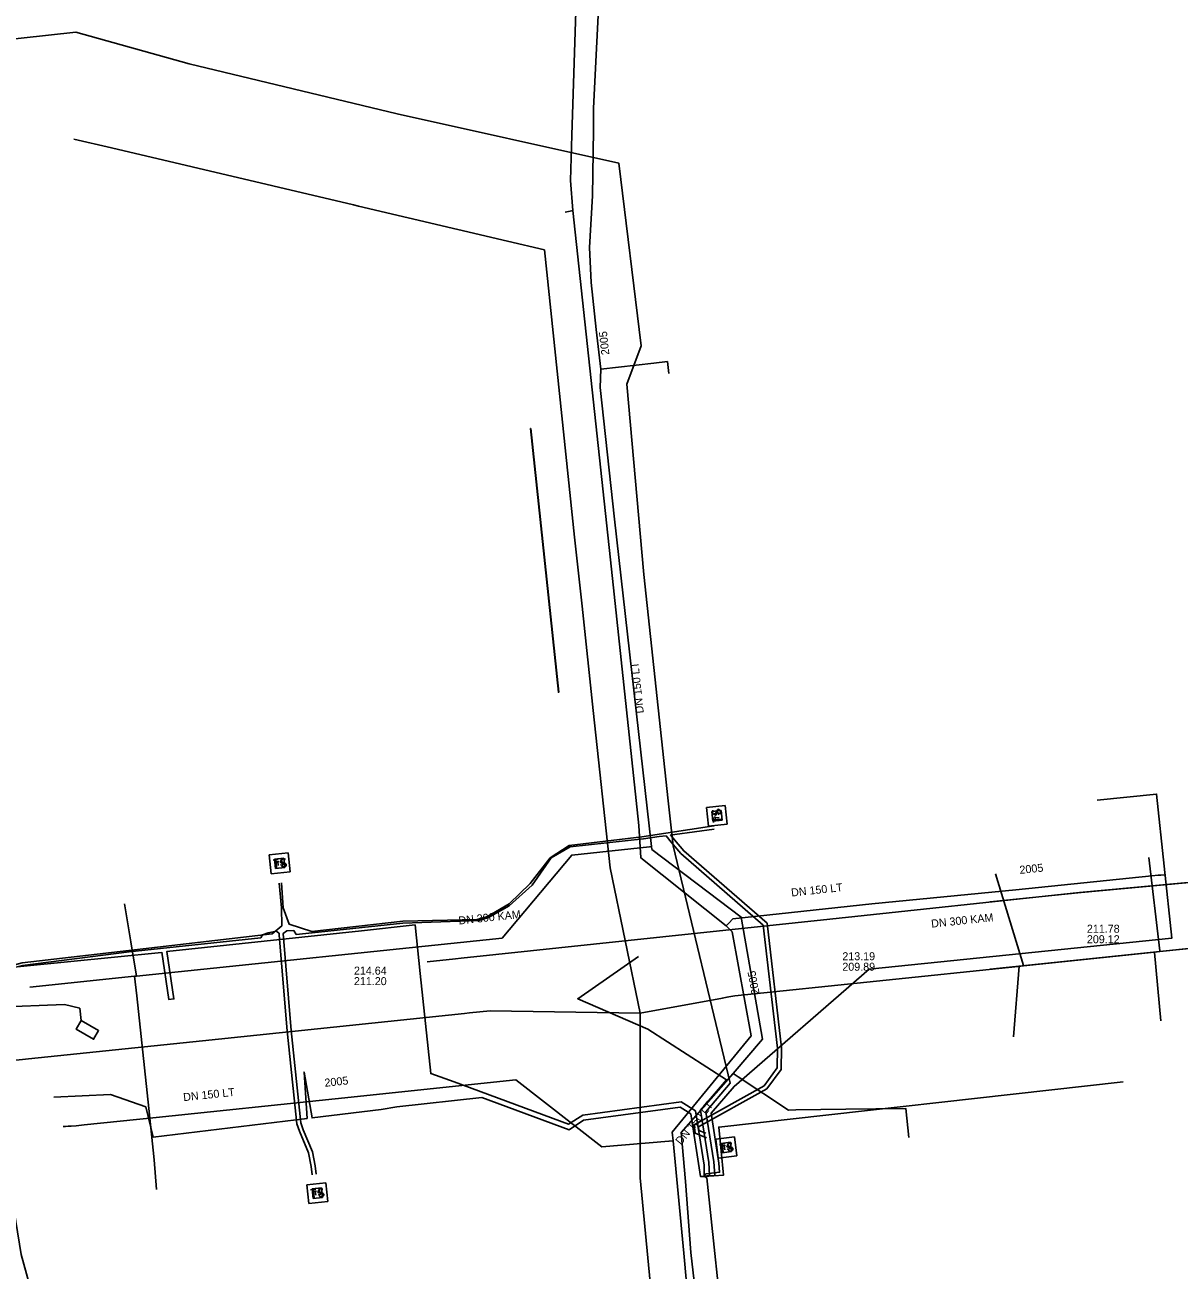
# Model space of a CAD drawing. Extents: x -599951 to -598963, y -1164095 to -1162939.
# Drawn here: x -599185.3 to -599070, y -1163320.1 to -1163195.6 of the extents above; entities that cross this region are included whole.
import ezdxf

# ---------------------------------------------------------------- set-up
doc = ezdxf.new("R2010")
doc.units = 0
for name, color, linetype in [('25', 7, 'Continuous'), ('Level 1', 7, 'Continuous'), ('Level 3', 7, 'Continuous'), ('Vrstva 1', 7, 'Continuous'), ('Vrstva 13', 7, 'Continuous'), ('Vrstva 15', 7, 'Continuous'), ('Vrstva 19', 7, 'Continuous'), ('Vrstva 42', 7, 'Continuous'), ('Vrstva 43', 7, 'Continuous'), ('Vrstva 44', 7, 'Continuous'), ('Vrstva 45', 7, 'Continuous'), ('Vrstva 5', 7, 'Continuous'), ('Vrstva 55', 7, 'Continuous'), ('Vrstva 8', 7, 'Continuous')]:
    doc.layers.add(name, color=color, linetype=linetype)

# ---------------------------------------------------------------- blocks, each defined once
blk = doc.blocks.new('VN640')
at = {"layer": '25'}
for points in [[(-1.89, 1.889), (1.889, 1.889)], [(-1.89, -1.89), (-1.89, 1.889)], [(-1.26, 0.787), (-0.221, 0.787)], [(-0.725, 0.787), (-0.725, -0.788)], [(1.197, 0.661), (0.945, 0.787), (0.661, 0.787), (0.409, 0.661), (0.283, 0.472), (0.283, 0.409), (0.409, 0.22), (1.133, -0.158), (1.259, -0.316), (1.259, -0.473), (1.133, -0.662), (0.913, -0.788), (0.629, -0.788), (0.503, -0.725), (0.283, -0.599)], [(1.889, 1.889), (1.889, -1.89)], [(1.889, -1.89), (-1.89, -1.89)]]:
    blk.add_lwpolyline(points, dxfattribs=at)
blk = doc.blocks.new('NN640')
at = {"layer": '25'}
for points in [[(-1.89, 1.889), (1.889, 1.889)], [(-1.89, -1.89), (-1.89, 1.889)], [(-1.26, 0.787), (-0.221, 0.787)], [(-0.725, 0.787), (-0.725, -0.788)], [(1.197, 0.661), (0.945, 0.787), (0.661, 0.787), (0.409, 0.661), (0.283, 0.472), (0.283, 0.409), (0.409, 0.22), (1.133, -0.158), (1.259, -0.316), (1.259, -0.473), (1.133, -0.662), (0.913, -0.788), (0.629, -0.788), (0.503, -0.725), (0.283, -0.599)], [(1.889, 1.889), (1.889, -1.89)], [(1.889, -1.89), (-1.89, -1.89)]]:
    blk.add_lwpolyline(points, dxfattribs=at)

msp = doc.modelspace()

# ---------------------------------------------------------------- linework, layer by layer
at = {"layer": 'Level 1'}
for points in [[(-599073.04, -1163278.86), (-599071.92, -1163288.19)], [(-599088.87, -1163283.31), (-599079.8, -1163282.35), (-599054.91, -1163280.08)], [(-599088.35, -1163280.51), (-599085.55, -1163289.65)], [(-599088.87, -1163290.03), (-599064.91, -1163287.54)], [(-599071.84, -1163295.18), (-599072.46, -1163288.36)], [(-599086.55, -1163296.78), (-599085.99, -1163289.73)], [(-599121.08, -1163339.75), (-599123.86, -1163310.87)]]:
    msp.add_lwpolyline(points, dxfattribs=at)
at = {"layer": 'Level 3'}
msp.add_lwpolyline([(-599134.774, -1163235.992), (-599131.993, -1163262.35), (-599132.026, -1163262.352), (-599134.809, -1163235.998)], close=True, dxfattribs=at)
at = {"layer": 'Vrstva 1'}
for p, q in [((-599133.4, -1163218.12), (-599130.4, -1163246.83)), ((-599126.86, -1163279.89), (-599123.848, -1163294.424)), ((-599138.824, -1163294.187), (-599123.848, -1163294.424)), ((-599123.86, -1163310.87), (-599123.848, -1163294.424))]:
    msp.add_line(p, q, dxfattribs=at)
for points in [[(-599180.431, -1163207.06), (-599176.662, -1163207.946), (-599152.489, -1163213.631), (-599151.996, -1163213.747), (-599137.108, -1163217.248), (-599133.4, -1163218.12)], [(-599130.4, -1163246.83), (-599129.66, -1163253.739), (-599128.542, -1163264.18), (-599126.86, -1163279.89)], [(-599114.398, -1163292.695), (-599086.084, -1163289.744), (-599085.537, -1163289.687), (-599072.458, -1163288.324), (-599071.911, -1163288.267), (-599065.048, -1163287.552)], [(-599123.848, -1163294.424), (-599115.628, -1163292.92), (-599115.185, -1163292.839), (-599114.398, -1163292.695)], [(-599167.579, -1163297.182), (-599141.41, -1163294.457), (-599140.913, -1163294.405), (-599138.824, -1163294.187)], [(-599188.263, -1163299.327), (-599185.582, -1163299.049), (-599184.986, -1163298.987), (-599167.579, -1163297.182)]]:
    msp.add_lwpolyline(points, dxfattribs=at)
at = {"layer": 'Vrstva 13'}
for p, q in [((-599071.837, -1163280.62), (-599071.41, -1163280.59)), ((-599072.099, -1163280.646), (-599071.837, -1163280.62)), ((-599115.26, -1163285.71), (-599114.99, -1163285.42)), ((-599181.262, -1163305.746), (-599181.49, -1163305.76)), ((-599181, -1163305.73), (-599181.262, -1163305.746)), ((-599180.711, -1163305.708), (-599181, -1163305.73)), ((-599120.54, -1163307.19), (-599120.963, -1163307.228))]:
    msp.add_line(p, q, dxfattribs=at)
for points in [[(-599129.94, -1163183.95), (-599130.67, -1163206.65), (-599130.8, -1163211.19), (-599130.57, -1163214.21)], [(-599130.57, -1163214.21), (-599130.86, -1163214.27), (-599131.33, -1163214.37)], [(-599130.57, -1163214.21), (-599126.71, -1163250.03), (-599124, -1163275.68), (-599123.77, -1163278.9), (-599115.26, -1163285.71)], [(-599114.99, -1163285.42), (-599114.59, -1163284.99), (-599100.72, -1163283.51), (-599086.3, -1163282.09), (-599072.73, -1163280.71), (-599072.099, -1163280.646)], [(-599115.26, -1163285.71), (-599114.66, -1163286.31), (-599112.76, -1163296.68), (-599120.64, -1163306.32), (-599120.54, -1163307.19)], [(-599120.963, -1163307.228), (-599120.99, -1163307.23), (-599127.67, -1163307.77), (-599136.28, -1163301.09), (-599154.33, -1163302.99), (-599172.22, -1163304.86), (-599179.403, -1163305.585), (-599180.21, -1163305.67), (-599180.711, -1163305.708)], [(-599120.54, -1163307.19), (-599119.5, -1163318.42), (-599118.91, -1163324.7), (-599114.698, -1163364.679), (-599114.5, -1163366.64)]]:
    msp.add_lwpolyline(points, dxfattribs=at)
at = {"layer": 'Vrstva 19'}
for points in [[(-599126.75, -1163162.08), (-599126.79, -1163163.73), (-599127.2, -1163178.52), (-599127.22, -1163178.72), (-599127.28, -1163179.39), (-599127.45, -1163182.79), (-599127.55, -1163184.72), (-599128.5, -1163203.98), (-599128.53, -1163206.15), (-599128.61, -1163212.73), (-599128.92, -1163217.9), (-599128.75, -1163221.4), (-599128.24, -1163226.08), (-599127.78, -1163230.06), (-599127.84, -1163231.89), (-599126.43, -1163245.05), (-599122.72, -1163277.78), (-599122.68, -1163278.05), (-599113.77, -1163284.82), (-599111.62, -1163297.03), (-599114.57, -1163300.46), (-599119.76, -1163306.35), (-599119.31, -1163311.26)], [(-599127.78, -1163230.06), (-599122.47, -1163229.45)], [(-599122.47, -1163229.45), (-599121.13, -1163229.29), (-599120.98, -1163230.49)], [(-599122.92, -1163277.8), (-599130.68, -1163278.63), (-599137.65, -1163286.92), (-599174.17, -1163290.72), (-599174.37, -1163290.74), (-599184.83, -1163291.83)], [(-599122.72, -1163277.78), (-599122.92, -1163277.8)], [(-599175.38, -1163283.5), (-599174.74, -1163287.31), (-599174.17, -1163290.72)], [(-599174.37, -1163290.74), (-599174.16, -1163292.69), (-599172.95, -1163303.94), (-599172.4, -1163309.1), (-599172.18, -1163312.05)], [(-599114.57, -1163300.46), (-599114.06, -1163300.79), (-599109.02, -1163304.11), (-599108.3, -1163304.1)], [(-599108.299, -1163304.101), (-599103.302, -1163304.026), (-599097.308, -1163303.938), (-599097.018, -1163306.838)], [(-599119.31, -1163311.26), (-599118.79, -1163318.36), (-599116.95, -1163334.26), (-599115.29, -1163352.21), (-599112.46, -1163377.65), (-599112.44, -1163377.84)]]:
    msp.add_lwpolyline(points, dxfattribs=at)
at = {"layer": 'Vrstva 42'}
for p, q in [((-599190.603, -1163293.916), (-599181.368, -1163293.563)), ((-599181.368, -1163293.563), (-599179.853, -1163293.926))]:
    msp.add_line(p, q, dxfattribs=at)
for points in [[(-599189.356, -1163255.904), (-599189.27, -1163255.9), (-599188.93, -1163256.56), (-599189.33, -1163266.86), (-599190.19, -1163270.28), (-599190.39, -1163272.54), (-599189.34, -1163289.98), (-599189, -1163294.5), (-599187.674, -1163304.188), (-599186.96, -1163310.71), (-599185.69, -1163318.54), (-599183.37, -1163327.02), (-599181.88, -1163329.78), (-599181.18, -1163331.7), (-599178.4, -1163350.09), (-599176.426, -1163364.646), (-599174.91, -1163374.22), (-599174.01, -1163382.86), (-599173.53, -1163386.1), (-599173.83, -1163387.31), (-599174.41, -1163387.97), (-599176.305, -1163391.004)], [(-599179.853, -1163293.926), (-599179.701, -1163295.167), (-599180.202, -1163296.032), (-599178.471, -1163297.034), (-599177.97, -1163296.169), (-599179.701, -1163295.167)]]:
    msp.add_lwpolyline(points, dxfattribs=at)
at = {"layer": 'Vrstva 44'}
for points in [[(-599161.6, -1163286.61), (-599161.768, -1163286.882), (-599174.92, -1163288.29), (-599185.56, -1163289.67), (-599188.76, -1163290.47), (-599253.7, -1163297.18), (-599254.76, -1163296.51), (-599255.896, -1163293.057), (-599256.264, -1163290.876), (-599256.287, -1163290.145), (-599256.603, -1163287.926), (-599258.874, -1163253.063), (-599260.496, -1163226.149), (-599261.652, -1163202.746), (-599261.6, -1163195.999), (-599261.001, -1163188.45)], [(-599159.684, -1163281.406), (-599159.52, -1163283.88), (-599158.92, -1163285.54), (-599156.65, -1163286.27), (-599147.57, -1163285.24), (-599140.14, -1163285.05), (-599139.09, -1163284.76), (-599136.95, -1163283.51), (-599134.83, -1163281.46), (-599132.83, -1163278.91), (-599130.96, -1163277.65), (-599123.67, -1163276.79), (-599116.496, -1163275.683)], [(-599121.256, -1163276.69), (-599121.952, -1163276.782), (-599123.52, -1163277), (-599130.84, -1163277.79), (-599132.75, -1163278.89), (-599134.64, -1163281.64), (-599136.94, -1163283.68), (-599139, -1163284.87), (-599139.96, -1163285.16), (-599147.57, -1163285.44), (-599156.62, -1163286.41), (-599158.212, -1163286.547), (-599158.45, -1163286.17)], [(-599117.236, -1163306.876), (-599118.365, -1163306.421), (-599118.464, -1163305.57), (-599111.475, -1163301.676), (-599110.149, -1163299.902), (-599110.12, -1163297.92), (-599111.55, -1163285.64), (-599119.783, -1163278.481), (-599120.745, -1163277.346), (-599121.256, -1163276.69)], [(-599116.458, -1163276.026), (-599120.384, -1163276.567), (-599120.812, -1163276.615)], [(-599120.812, -1163276.615), (-599120.424, -1163277.106), (-599119.497, -1163278.199), (-599111.17, -1163285.44), (-599109.72, -1163297.9), (-599109.751, -1163300.038), (-599111.205, -1163301.984), (-599118.036, -1163305.79), (-599117.995, -1163306.139), (-599117.287, -1163306.423)], [(-599252.79, -1163297.02), (-599251.6, -1163296.924), (-599251.285, -1163296.822), (-599250.535, -1163296.649), (-599188.84, -1163290.26), (-599185.61, -1163289.38), (-599174.94, -1163288.15), (-599160.62, -1163286.51), (-599159.66, -1163285.71), (-599159.7, -1163283.9), (-599159.915, -1163281.43)], [(-599156.618, -1163310.576), (-599156.728, -1163309.742), (-599156.983, -1163308.398), (-599157.907, -1163306.21), (-599158.147, -1163305.482), (-599159.109, -1163296.179), (-599159.91, -1163286.622), (-599159.916, -1163286.446), (-599160.2, -1163286.22), (-599161.01, -1163286.39), (-599161.6, -1163286.61)], [(-599158.45, -1163286.17), (-599159.15, -1163286.18), (-599159.514, -1163286.459), (-599158.711, -1163296.141), (-599157.753, -1163305.398), (-599157.533, -1163306.07), (-599156.597, -1163308.282), (-599156.332, -1163309.678), (-599156.222, -1163310.524)]]:
    msp.add_lwpolyline(points, dxfattribs=at)
at = {"layer": 'Vrstva 5'}
msp.add_line((-599104.903, -1163285.017), (-599079.945, -1163282.356), dxfattribs=at)
for points in [[(-599079.945, -1163282.356), (-599067.297, -1163281.206), (-599066.7, -1163281.152), (-599054.91, -1163280.08)], [(-599145.141, -1163289.279), (-599142.307, -1163288.979), (-599141.75, -1163288.92), (-599104.903, -1163285.017)]]:
    msp.add_lwpolyline(points, dxfattribs=at)
at = {"layer": 'Vrstva 55'}
for points in [[(-599117.475, -1163310.719), (-599116.403, -1163310.664), (-599116.506, -1163309.289), (-599117.29, -1163304.271), (-599114.85, -1163301.425), (-599120.56, -1163277.69), (-599121.07, -1163273.2), (-599123.48, -1163250.59), (-599125.17, -1163231.54), (-599123.76, -1163227.71), (-599125.97, -1163209.48), (-599148.12, -1163204.54), (-599168.91, -1163199.53), (-599180.245, -1163196.375), (-599191.5, -1163197.6)], [(-599117.516, -1163310.513), (-599115.909, -1163310.32), (-599115.979, -1163309.422), (-599116.761, -1163304.421), (-599114.47, -1163301.75), (-599100.96, -1163290.02), (-599070.74, -1163286.93), (-599072.25, -1163272.53), (-599078.19, -1163273.15)], [(-599117.448, -1163310.705), (-599117.469, -1163309.6), (-599118.314, -1163304.197), (-599119.74, -1163303.3), (-599129.59, -1163304.61), (-599131, -1163305.52), (-599142.43, -1163301.3), (-599144.78, -1163300.47), (-599145.83, -1163290.46), (-599146.34, -1163285.6), (-599151.7, -1163286.18), (-599171.151, -1163288.276), (-599170.444, -1163292.994), (-599170.94, -1163293.07), (-599171.65, -1163288.33)], [(-599171.684, -1163288.363), (-599190.497, -1163290.222), (-599196.05, -1163289.34)], [(-599117.461, -1163310.719), (-599116.926, -1163310.636), (-599117.003, -1163309.346), (-599117.82, -1163304.12), (-599115.23, -1163301.1), (-599123.09, -1163296.01), (-599130.09, -1163292.98), (-599124.02, -1163288.77)], [(-599117.496, -1163310.745), (-599117.838, -1163310.745), (-599118.773, -1163304.499), (-599119.853, -1163303.819), (-599129.524, -1163305.106), (-599130.939, -1163306.076), (-599139.685, -1163302.846), (-599148.15, -1163303.78), (-599149.74, -1163304.06), (-599156.634, -1163304.892), (-599157.44, -1163300.31), (-599157.131, -1163304.952), (-599172.52, -1163306.81), (-599173.26, -1163303.8), (-599176.79, -1163302.55), (-599182.44, -1163302.81)], [(-599117.461, -1163310.746), (-599115.538, -1163310.623), (-599116.004, -1163305.812), (-599075.589, -1163301.297)], [(-599056.04, -1163381.08), (-599057.521, -1163382.067), (-599063, -1163381.34), (-599075.63, -1163379.84), (-599077.47, -1163379.54), (-599078.92, -1163380.19), (-599086.95, -1163380.89), (-599098.38, -1163382.72), (-599107.35, -1163383.43), (-599108.05, -1163378.25), (-599110.02, -1163365.67), (-599111.33, -1163356.15), (-599110.48, -1163355.08), (-599111.65, -1163354.31), (-599112.89, -1163352), (-599114.84, -1163333.25), (-599116.75, -1163314.99), (-599117.2, -1163310.89), (-599117.468, -1163310.717), (-599117.311, -1163310.489)]]:
    msp.add_lwpolyline(points, dxfattribs=at)

# ---------------------------------------------------------------- block references
at = {"layer": 'Vrstva 43', "xscale": 0.5}
for p, yscale, rotation in [((-599116.187, -1163274.701), 0.5, 96), ((-599159.867, -1163279.446), 0.5000000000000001, 6), ((-599115.239, -1163307.853), 0.5000000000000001, 6.999999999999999), ((-599156.11, -1163312.413), 0.5000000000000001, 6)]:
    msp.add_blockref('NN640', p, dxfattribs=dict(at, yscale=yscale, rotation=rotation))
at = {"layer": 'Vrstva 45', "xscale": 0.25}
for p, yscale, rotation in [((-599116.187, -1163274.701), 0.25, 96), ((-599159.867, -1163279.446), 0.25000000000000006, 6), ((-599115.239, -1163307.853), 0.25000000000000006, 7), ((-599156.11, -1163312.413), 0.25000000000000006, 6)]:
    msp.add_blockref('VN640', p, dxfattribs=dict(at, yscale=yscale, rotation=rotation))

# ---------------------------------------------------------------- texts
at = {"layer": 'Vrstva 15'}
for s, rotation, p in [('2005', 96.14232, (-599126.927, -1163228.591)), ('DN 150 LT', 96.02773, (-599123.486, -1163264.423)), ('2005', 5.78687, (-599085.906, -1163280.507)), ('DN 150 LT', 6.07335, (-599108.726, -1163282.77)), ('2005', 100.38221, (-599111.917, -1163292.477)), ('2005', 6.01606, (-599155.349, -1163301.785)), ('DN 150 LT', 5.95876, (-599169.468, -1163303.222)), ('DN 150 LT', 50.76406, (-599119.78, -1163307.646))]:
    msp.add_text(s, height=0.8, rotation=rotation, dxfattribs=at).set_placement(p)
at = {"layer": 'Vrstva 8'}
for p in [(-599141.962, -1163285.572), (-599094.731, -1163285.88)]:
    msp.add_text('DN 300 KAM', height=0.8, rotation=6.07335, dxfattribs=at).set_placement(p)
for s, p in [('211.78', (-599079.214, -1163286.383)), ('209.12', (-599079.214, -1163287.433)), ('213.19', (-599103.651, -1163289.134)), ('214.64', (-599152.452, -1163290.572)), ('209.89', (-599103.651, -1163290.184)), ('211.20', (-599152.452, -1163291.622))]:
    msp.add_text(s, height=0.8, dxfattribs=at).set_placement(p)

doc.saveas('drawing.dxf')
